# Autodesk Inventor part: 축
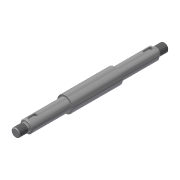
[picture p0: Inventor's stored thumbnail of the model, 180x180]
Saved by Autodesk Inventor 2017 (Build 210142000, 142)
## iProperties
Created: 2018-11
Part Number: 축
Material: 강철, 연강
Document SubType Name: Modeling
Designer: mduedu
Density: 1 g/cm^3
Appearance: Steel
Author: mduedu
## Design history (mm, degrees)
sketch "스케치1"
  geometry: L1 (-35, 0)-(35, 0); L2 (35, 0)-(35, 11); L3 (35, 11)-(-35, 11); L4 (-35, 11)-(-35, 0); L5 (-35, 0)-(-90, 0); L6 (-90, 0)-(-90, 8.5); L7 (-90, 8.5)-(-35, 8.5); L8 (-35, 8.5)-(-35, 0); L9 (-90, 0)-(-105, 0); L10 (-105, 0)-(-105, 6); L11 (-105, 6)-(-90, 6); L12 (-90, 6)-(-90, 0); L13 (0, 0)-(0, 11); L14 (35, 0)-(90, 0); L15 (90, 0)-(90, 8.5); L16 (90, 8.5)-(35, 8.5); L17 (35, 8.5)-(35, 0); L18 (90, 0)-(105, 0); L19 (105, 0)-(105, 6); L20 (105, 6)-(90, 6); L21 (90, 6)-(90, 0); 1 further point
  constraints: 42 end point, 6 parallel, 6 symmetric about line, 3 horizontal, 3 perpendicular, 2 midpoint, 1 coincident
  dimensions: "d0" = 22 diameter of L3 L1; "d2" = 17 diameter of L7 L5; "d3" = 12 diameter of L11 L9; "d4" = 70 distance of L2.end L3.end; "d5" = 55 distance of L6.end L7.end; "d6" = 210 distance between parallel lines of L19 L10
revolve "회전1" sketch "스케치1" stored, may be unused: angle "d7" = 90 deg
fillet "모깎기1" dims "d8" = 0.3
node "작업 평면1"
sketch "스케치2" dims "d11" = 12
  geometry: L1 (15, 2.5)-(22, 2.5); L2 (22, 2.5)-(22, -2.5); L3 (22, -2.5)-(15, -2.5); L4 (15, -2.5)-(15, 2.5); L5 (27.5, 8.5)-(27.5, -8.5) reference; 3 further points
  constraints: 8 end point, 2 midpoint, 2 parallel, 2 vertical alignment, 1 horizontal, 1 horizontal alignment, 1 perpendicular, 4 other
  dimensions: "d9" = 3 dimension on L5; "d10" = 5 distance between parallel lines of L3 L1
extrude "돌출1" cut sketch "스케치2" distance "d12" = 3; taper "d13" = 0 deg
chamfer "모따기1" distance "d14" = 1; stored, may be unused: second distance "d15" = 2, angle "d16" = 45 deg
feature "스레드1" dims "d17" = 12, "d18" = 0
feature "스레드2" dims "d19" = 12, "d20" = 0
chamfer "모따기2" distance "d21" = 1; stored, may be unused: second distance "d22" = 2, angle "d23" = 45 deg
node "솔리드1"
mirror "대칭1"
